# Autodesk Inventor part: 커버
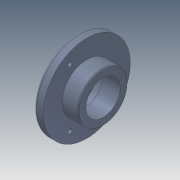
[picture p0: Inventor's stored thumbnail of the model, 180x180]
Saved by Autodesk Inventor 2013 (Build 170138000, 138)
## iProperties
Company: 한국ATC센터
Created: 2014-10
Part Number: 커버
Document SubType Name: Modeling
Designer: 한국ATC센터
Density: 2.71 g/cm^3
Material: 알루미늄-6061
Mass: 189.975 g
Surface Area: 197.126 cm^2
Volume: 70.1013 cm^3
Author: KYOUNG IL JANG
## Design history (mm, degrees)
sketch "스케치1"
  geometry: L1 (-13.5, 0)-(13.5, 0); L2 (-13.5, 0)-(-13.5, 45.5); L3 (-13.5, 45.5)-(-3.5, 45.5); L4 (-3.5, 45.5)-(-3.5, 26); L5 (-3.5, 26)-(13.5, 26); L6 (13.5, 26)-(13.5, 0); 2 further points
  constraints: 12 end point, 3 parallel, 2 perpendicular, 1 coincident, 1 horizontal, 1 midpoint
  dimensions: "d0" = 27 distance of L1.start L1.end; "d1" = 91 diameter of L3 L1; "d2" = 52 diameter of L5 L1; "d3" = 10 distance of L2.end L3.end
revolve "회전1" sketch "스케치1" stored, may be unused: angle "d4" = 90 deg
hole "구멍1" diameter "d7" = 36; stored, may be unused: countersink angle "d11" = 90 deg, drill point angle "d13" = 118 deg; dims "d5" = 10, "d6" = 10, "d8" = 6, "d9" = 40, "d10" = 8.3, "d12" = 8
sketch "스케치2"
  geometry: 2 further points
  constraints: 1 vertical alignment
  dimensions: "d14" = 35 distance of point (0, 0) point (0, 35)
hole "구멍2" sketch "스케치2" at (0, 35) diameter "d15" = 4.5; stored, may be unused: countersink angle "d19" = 90 deg, drill point angle "d21" = 118 deg; dims "d16" = 6, "d17" = 8, "d18" = 4.4, "d20" = 8
chamfer "모따기1" distance "d25" = 0.8; stored, may be unused: second distance "d26" = 2, angle "d27" = 30 deg
fillet "모깎기1" dims "d28" = 0.1, "d29" = 3
chamfer "모따기2" distance "d30" = 1; stored, may be unused: second distance "d31" = 2, angle "d32" = 30 deg
node "솔리드1"
pattern_circular "원형 패턴1" dims angle "d23" = 360 deg
